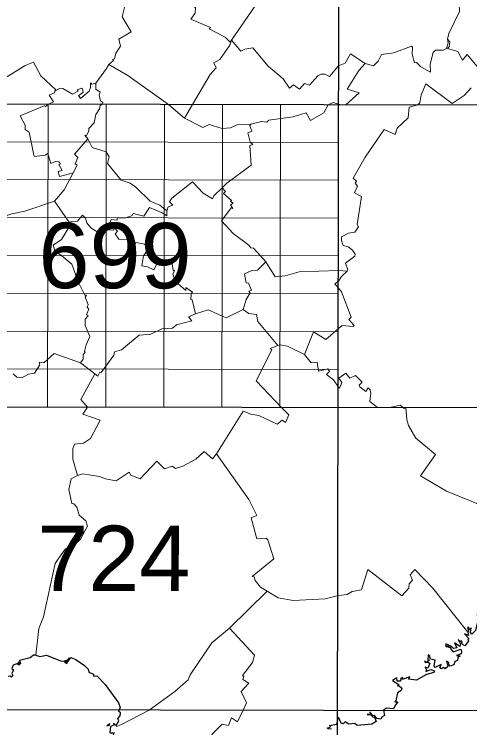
# Model space of a CAD drawing. Extents: x 483847 to 488453, y 4383581 to 4386795.
# Drawn here: x 488155.4 to 488291.2, y 4385556 to 4385768.9 of the extents above; entities that cross this region are included whole.
import ezdxf
from ezdxf.enums import TextEntityAlignment as Align

# ---------------------------------------------------------------- set-up
doc = ezdxf.new("R2010")
doc.units = 0
doc.header["$LTSCALE"] = 3.8
doc.linetypes.add('DOTTED', pattern=[1.5, 0.3, -1.2])
for name, color, linetype, lineweight in [('1', 7, 'Continuous', 13), ('2', 7, 'DOTTED', 13), ('3', 7, 'Continuous', 25)]:
    doc.layers.add(name, color=color, linetype=linetype, lineweight=lineweight)

msp = doc.modelspace()

# ---------------------------------------------------------------- linework, layer by layer
at = {"layer": '1', "lineweight": 25}
for p, q in [((488251.44, 4385380.63), (488252.47, 4385922.58)), ((487836.45, 4385742.71), (488390.69, 4385741.65)), ((487836.28, 4385652.38), (488390.51, 4385651.32)), ((487836.1, 4385562.06), (488390.34, 4385561))]:
    msp.add_line(p, q, dxfattribs=at)
at = {"layer": '1'}
for p, q in [((488165.35, 4385651.74), (488165.52, 4385742.07)), ((488182.67, 4385651.71), (488182.84, 4385742.03)), ((488199.99, 4385651.68), (488200.16, 4385742)), ((488217.31, 4385651.64), (488217.49, 4385741.97)), ((488234.63, 4385651.61), (488234.8, 4385741.93)), ((488252.1, 4385730.61), (488113.54, 4385730.88)), ((488252.08, 4385719.32), (488113.52, 4385719.58)), ((488252.06, 4385708.03), (488113.5, 4385708.3)), ((488252.04, 4385696.74), (488113.48, 4385697)), ((488252.02, 4385685.45), (488113.45, 4385685.72)), ((488252, 4385674.16), (488113.43, 4385674.42)), ((488251.98, 4385662.87), (488113.41, 4385663.13))]:
    msp.add_line(p, q, dxfattribs=at)
at = {"layer": '3', "lineweight": 13}
for p, q in [((488182.87, 4385752.64), (488179.74, 4385748.27)), ((488206.19, 4385737.81), (488201.41, 4385741.93)), ((488252.94, 4385741.87), (488252.13, 4385742.06)), ((488254.34, 4385741.87), (488252.94, 4385741.87)), ((488167.44, 4385713.07), (488171.98, 4385706.56)), ((488182.88, 4385704.56), (488182.76, 4385703.83)), ((488228.86, 4385696.74), (488230.45, 4385694.99)), ((488263.74, 4385651.55), (488267.38, 4385651.56)), ((488230.78, 4385596.71), (488219.58, 4385585.66))]:
    msp.add_line(p, q, dxfattribs=at)
for points in [[(488220.21, 4385761.13), (488228.13, 4385772.7), (488232.82, 4385777.75), (488239.16, 4385785.97), (488239.66, 4385785.89), (488240.55, 4385787.05)], [(488199.2, 4385781.34), (488200.15, 4385779.29), (488200.39, 4385776.63), (488201.82, 4385774.42), (488203.14, 4385774.79), (488203.29, 4385775.73), (488204.67, 4385774.91), (488204.43, 4385774.47), (488207.94, 4385772.21), (488209.43, 4385770.78), (488209.32, 4385769.17), (488208.03, 4385767.44), (488213.88, 4385764.91), (488213.53, 4385764.55), (488218.26, 4385761.99), (488219.77, 4385760.56), (488220.21, 4385761.13)], [(488190.94, 4385776.16), (488189.53, 4385775.57), (488188.44, 4385774.48), (488187.53, 4385772.28), (488188.32, 4385770.85), (488187.6, 4385768.1), (488190.22, 4385763.57), (488186.56, 4385761.41), (488187.11, 4385759.29), (488185.74, 4385757.3), (488185.26, 4385755.51), (488184.68, 4385755.33), (488184.99, 4385755.05), (488183.63, 4385753.87), (488182.87, 4385752.64)], [(488289.37, 4385776.95), (488289.54, 4385775.88), (488288.46, 4385773.74), (488288.11, 4385772.01), (488288.17, 4385769.68), (488285.03, 4385763.14), (488284.6, 4385761.41)], [(488220.21, 4385761.13), (488219.67, 4385759.59), (488216.71, 4385755.4), (488214.9, 4385754.32), (488215.58, 4385752.84), (488213.86, 4385750.9), (488208.54, 4385741.92)], [(488220.21, 4385761.13), (488222.99, 4385757.82), (488224.17, 4385758.43), (488226.59, 4385758.8), (488231.1, 4385753.33), (488235.59, 4385749.63), (488237.46, 4385746.82), (488238.65, 4385747.8), (488240.51, 4385746.55), (488241.92, 4385748.2), (488243.49, 4385747.75), (488245.97, 4385750.53), (488246.96, 4385751.03), (488248, 4385750.97), (488249.38, 4385750.24), (488252.13, 4385753.5)], [(488284.6, 4385761.41), (488284.82, 4385760.34), (488284.3, 4385758.65), (488283.28, 4385758.15), (488281.03, 4385758.11), (488280.3, 4385757.41), (488279.42, 4385753.98), (488279.57, 4385751.54), (488276.66, 4385753.14), (488275.39, 4385754.5), (488274.74, 4385754.41), (488274.1, 4385757), (488274.19, 4385759.07), (488273.86, 4385759.37), (488268.65, 4385757.32), (488264.89, 4385756.83), (488263.98, 4385754.82), (488262.51, 4385753.5), (488260.05, 4385754.13)], [(488284.6, 4385761.41), (488285.27, 4385760.6), (488285.14, 4385759.17), (488284.57, 4385758.65), (488287.69, 4385757.73), (488289.13, 4385755.16), (488290.47, 4385756.9), (488295.44, 4385750.84)], [(488260.05, 4385754.13), (488255.65, 4385757.08), (488254.12, 4385754.29), (488252.13, 4385753.5)], [(488167.53, 4385745.92), (488167.8, 4385746.29), (488163.29, 4385750.45), (488161.13, 4385754.57), (488158.69, 4385753.6), (488153.35, 4385750.3), (488151.64, 4385751.38)], [(488183.63, 4385753.87), (488189.28, 4385750.6), (488201.41, 4385741.93)], [(488260.05, 4385754.13), (488258.18, 4385752.05), (488254.71, 4385746.47), (488258.28, 4385745.37), (488254.34, 4385741.87)], [(488179.74, 4385748.27), (488178.55, 4385747.96), (488178.1, 4385748.41), (488178.17, 4385747.03), (488177.74, 4385745.92), (488175.13, 4385743.73), (488174.55, 4385744.59), (488175.95, 4385745.5), (488175.77, 4385746.65), (488175.46, 4385746.8), (488174.13, 4385746.28), (488174.42, 4385745.95), (488172.72, 4385745.01), (488169.9, 4385746.75), (488169.07, 4385746.77), (488167.53, 4385745.92)], [(488179.74, 4385748.27), (488179.77, 4385746.53), (488181.02, 4385745.63), (488180.72, 4385744.78), (488181.14, 4385742.9), (488181.8, 4385742.63), (488181.51, 4385741.96)], [(488291.72, 4385746.88), (488289.56, 4385744.65), (488286.02, 4385742.23), (488278.18, 4385748.08), (488276.81, 4385744.8), (488276.4, 4385742.39), (488275.8, 4385741.88)], [(488167.53, 4385745.92), (488167.38, 4385745.42), (488165.82, 4385744.74), (488167.09, 4385742.69), (488165.64, 4385742.01)], [(488165.64, 4385742.01), (488164.67, 4385741.33), (488164.3, 4385741.58), (488157.18, 4385738.51), (488158.67, 4385735.77), (488158.65, 4385734.48), (488159.84, 4385733.64), (488161.2, 4385726.8), (488161.41, 4385726.4), (488164.58, 4385726.77), (488165.45, 4385727.34), (488166.31, 4385724.38), (488167.56, 4385724.96), (488168.72, 4385724.85), (488169.16, 4385724.2), (488168.73, 4385724.06), (488169.66, 4385722.2), (488168.52, 4385721.98), (488168.84, 4385720.48), (488172.99, 4385721.58)], [(488181.51, 4385741.96), (488180.97, 4385741.62), (488180.79, 4385740.64), (488179.76, 4385738.93), (488179.18, 4385736.44), (488177.67, 4385734.77), (488177.65, 4385733.94), (488176.93, 4385732.73), (488176.42, 4385732.78), (488177.32, 4385731.73)], [(488225.99, 4385736.06), (488221.89, 4385735.87), (488219.86, 4385734.99), (488217.42, 4385734.73), (488213.57, 4385735.98), (488211.65, 4385735.09), (488206.19, 4385737.81), (488208.54, 4385741.92)], [(488225.99, 4385736.06), (488229.14, 4385736.86), (488230.71, 4385736.63), (488231.34, 4385737.24), (488238.57, 4385738.25), (488242.47, 4385739.4), (488243.73, 4385737.13), (488247.74, 4385739.4), (488249.07, 4385741.87)], [(488252.13, 4385742.06), (488250.48, 4385742.54), (488249.07, 4385741.87)], [(488275.8, 4385741.88), (488273.2, 4385741.15), (488272.87, 4385738), (488269.56, 4385734.91), (488269.01, 4385733.03), (488265.72, 4385734.46), (488260.05, 4385726.19), (488256.45, 4385720), (488257.51, 4385719.05), (488257.11, 4385718.51), (488257.76, 4385717.61), (488256.84, 4385715.54), (488258.98, 4385714.46), (488257.65, 4385706.15), (488258.04, 4385705.45), (488256.99, 4385703.81), (488255.04, 4385703.5), (488253.01, 4385702.47), (488252.98, 4385701.32), (488253.48, 4385699.88), (488255.01, 4385699.45), (488256.3, 4385698.51), (488257.11, 4385697.33), (488256.96, 4385696.71)], [(488217.44, 4385717.08), (488218.77, 4385718.45), (488226.04, 4385723.83), (488225.68, 4385729.71), (488226.55, 4385730.03), (488225.79, 4385730.74), (488225.02, 4385733.46), (488226.23, 4385734.01), (488225.64, 4385735.61), (488225.99, 4385736.06)], [(488177.32, 4385731.73), (488173.37, 4385727.15), (488174.4, 4385726.12), (488173.57, 4385724.25), (488174.17, 4385723.81), (488172.99, 4385721.58)], [(488177.32, 4385731.73), (488178.65, 4385729.11), (488182.82, 4385727.84)], [(488182.82, 4385727.84), (488183.73, 4385726.3), (488183.23, 4385724.38), (488187.28, 4385719.4), (488189.92, 4385718.48), (488191.67, 4385717.25), (488195.94, 4385713.11), (488198.79, 4385711.92), (488200.94, 4385710.23)], [(488172.99, 4385721.58), (488170.28, 4385716.46), (488167.44, 4385713.07)], [(488200.94, 4385710.23), (488201.31, 4385711.45), (488202.74, 4385711.93), (488201.65, 4385712.87), (488202.35, 4385714.02), (488208.52, 4385718.83), (488211.77, 4385715.47), (488214.57, 4385713.81), (488214.97, 4385714.68), (488217.44, 4385717.08)], [(488217.44, 4385717.08), (488218.36, 4385715.96), (488217.8, 4385715.37), (488220.18, 4385713.34), (488219.87, 4385713.04), (488220.64, 4385712.45), (488219.94, 4385712.01), (488220.61, 4385710.93), (488220.11, 4385711.07), (488217.2, 4385707.18), (488220.71, 4385703.44), (488225.36, 4385699.95), (488225.96, 4385699.14), (488226.76, 4385699.07), (488228.86, 4385696.74)], [(488167.44, 4385713.07), (488158.57, 4385710.07), (488154.66, 4385709.36), (488152.11, 4385708.38), (488150.26, 4385711.36), (488146.26, 4385709.98), (488146.02, 4385710.9), (488144.44, 4385710.34), (488140.68, 4385707.94), (488139.48, 4385709.35), (488134.38, 4385707.9)], [(488182.88, 4385704.56), (488184.31, 4385707.61), (488186.01, 4385707.44), (488186.21, 4385708.1), (488188.65, 4385708.13), (488190.57, 4385708.83), (488190.88, 4385709.38), (488194.06, 4385708.61), (488195.76, 4385711.19), (488199.47, 4385709.66), (488200.88, 4385708.68), (488200.94, 4385710.23)], [(488171.98, 4385706.56), (488172.22, 4385706.94), (488174.28, 4385707.16), (488175.7, 4385708.91), (488176.68, 4385708.05), (488177.07, 4385706.67), (488178.28, 4385705.16), (488181.11, 4385703.33), (488182.76, 4385703.83)], [(488171.98, 4385706.56), (488172.29, 4385706.21), (488169.5, 4385701.66), (488166.99, 4385699.99), (488167.63, 4385698.21), (488169.6, 4385696.83)], [(488182.88, 4385704.56), (488185.12, 4385704.48), (488185.15, 4385705.23), (488186.2, 4385704.12), (488185.45, 4385703.35), (488186.56, 4385701.78), (488189.95, 4385701.63), (488191.29, 4385700.44), (488191.74, 4385700.79), (488194.25, 4385700.27), (488195.42, 4385698.88), (488193.92, 4385696.78)], [(488169.6, 4385696.83), (488172.53, 4385694.28), (488174.45, 4385689), (488176.46, 4385685.01), (488176.96, 4385685.03), (488176.56, 4385684.42), (488177.44, 4385682.24), (488177.18, 4385681.47), (488177.6, 4385680.92), (488176.95, 4385679.28), (488177.42, 4385678.9), (488176.52, 4385677.86), (488176.52, 4385676.02), (488177.93, 4385672.7), (488176.84, 4385670.28), (488176.31, 4385668.26), (488176.59, 4385668.09), (488175.96, 4385667.22), (488175.99, 4385665.95), (488175.14, 4385664.85)], [(488193.92, 4385696.78), (488193.43, 4385693.85), (488195.13, 4385693.53), (488196.99, 4385692.62), (488198.68, 4385695.85), (488201.41, 4385695.05), (488201.74, 4385695.24), (488201.77, 4385694.77), (488202.42, 4385695.01), (488202.81, 4385692.44), (488203.16, 4385692.37), (488202.69, 4385691.33), (488203.34, 4385689.24), (488206.58, 4385686.44), (488206.58, 4385687.33), (488208.54, 4385685.98), (488208.14, 4385685.43), (488208.09, 4385683.71), (488208.5, 4385683.67), (488209.47, 4385679.46)], [(488256.96, 4385696.71), (488254.23, 4385694.62), (488254.88, 4385692.6), (488254.67, 4385692.19), (488252.11, 4385692.42)], [(488230.45, 4385694.99), (488227.98, 4385692.5), (488226.05, 4385692.3), (488224.03, 4385691.43), (488224.56, 4385688.73), (488225.24, 4385688.65), (488226.2, 4385686.52), (488225.37, 4385686.22), (488225.73, 4385685.74), (488224.56, 4385683.76), (488223.68, 4385680.79)], [(488230.45, 4385694.99), (488233.21, 4385690.49), (488236.2, 4385690.77), (488240.35, 4385692.03), (488252.11, 4385692.42)], [(488254.67, 4385692.19), (488252.95, 4385690.65), (488252.11, 4385689.25)], [(488252.11, 4385689.25), (488251.03, 4385688.45), (488252.11, 4385687.12)], [(488252.11, 4385687.12), (488253.04, 4385686.01), (488255.87, 4385678.46), (488255.16, 4385677.75), (488256.76, 4385676.05), (488256.44, 4385675.69), (488253.15, 4385675.97), (488252.1, 4385675.15)], [(488209.47, 4385679.46), (488207.41, 4385678.55), (488208.31, 4385677.43), (488203.78, 4385676.23), (488202.62, 4385675.18), (488199.39, 4385674.96), (488196.11, 4385673.45), (488192.7, 4385673.13), (488187.34, 4385668.77), (488185.25, 4385668.14), (488185.05, 4385667.14), (488182.68, 4385663.82)], [(488223.68, 4385680.79), (488218.57, 4385678.33), (488213.2, 4385680.64), (488209.47, 4385679.46)], [(488223.68, 4385680.79), (488225.41, 4385679.63), (488227.63, 4385679.28), (488228.02, 4385677.18), (488233.98, 4385670.03)], [(488252.1, 4385675.15), (488248.36, 4385671.8), (488244.62, 4385674.1), (488241.93, 4385667.32)], [(488233.98, 4385670.03), (488231.72, 4385669.18), (488232.2, 4385668.73), (488227.58, 4385659.47), (488235.12, 4385651.57)], [(488241.93, 4385667.32), (488236.85, 4385669.8), (488234.57, 4385670.27), (488233.98, 4385670.03)], [(488155.03, 4385661.61), (488156.12, 4385660.59), (488157.68, 4385660.36), (488159.68, 4385661.52), (488161.42, 4385661.76), (488162.99, 4385664.28), (488162.78, 4385665.11), (488164.26, 4385664.83), (488167.34, 4385667.65), (488175.14, 4385664.85), (488179.41, 4385661.55)], [(488241.93, 4385667.32), (488243.99, 4385664.89), (488245.79, 4385665.03), (488246.09, 4385662.38), (488248.88, 4385663.07), (488249.42, 4385662.24), (488248.57, 4385661.42), (488250.57, 4385659.78), (488252.1, 4385657.64)], [(488182.68, 4385663.82), (488181.34, 4385662.02), (488180.95, 4385662.11), (488180.37, 4385660.91), (488179.41, 4385661.55)], [(488179.41, 4385661.55), (488175.21, 4385653.96), (488177.22, 4385651.65)], [(488252.1, 4385657.64), (488252.4, 4385657.27), (488253.14, 4385658.98), (488252.21, 4385660.29), (488254.26, 4385661.74), (488255.48, 4385660.3), (488257.14, 4385661.1), (488259.19, 4385659.07), (488258.28, 4385658.25), (488258.5, 4385657.73), (488260.28, 4385656.33), (488260.92, 4385657.36), (488261.51, 4385656.81), (488261.77, 4385655.84), (488261.44, 4385653.35), (488263.74, 4385651.55)], [(488174.26, 4385631.26), (488172.91, 4385636.17), (488172.85, 4385639.35), (488173.33, 4385640.63), (488176.04, 4385640.86), (488178.13, 4385642.27), (488181.02, 4385647.76), (488175.87, 4385649.57), (488177.22, 4385651.65)], [(488267.38, 4385651.56), (488270.45, 4385652.23), (488271.35, 4385651.56)], [(488215.69, 4385637.76), (488223.71, 4385650.47), (488225.92, 4385649.59), (488228.3, 4385649.2), (488233.82, 4385646.6), (488235.27, 4385647.74), (488236.27, 4385647.03), (488237.31, 4385649.36), (488235.12, 4385651.57)], [(488271.35, 4385651.56), (488271.67, 4385651.26), (488272.21, 4385651.43), (488272.45, 4385647.98), (488273.02, 4385646.18), (488275.13, 4385642.37), (488281.06, 4385637.53), (488276.54, 4385631.14), (488284.34, 4385626.54), (488305.36, 4385618.01), (488306.32, 4385618.01)], [(488182.6, 4385630.29), (488185.82, 4385629.68), (488189.64, 4385632.26), (488190.15, 4385631.39), (488192.95, 4385630.22), (488197.95, 4385635.51), (488200.24, 4385633.22), (488202.51, 4385634.06), (488203.46, 4385633.3), (488205.7, 4385634.07), (488209.58, 4385636.1), (488212.08, 4385638.38), (488214.53, 4385636.22), (488215.69, 4385637.76)], [(488215.69, 4385637.76), (488225.39, 4385624.05), (488227.77, 4385619.31), (488226.1, 4385618.61), (488227.77, 4385612.4), (488230.55, 4385612.57), (488230.99, 4385612.07), (488232.79, 4385606.4)], [(488174.26, 4385631.26), (488172.41, 4385630.27), (488171.68, 4385627.03), (488172.59, 4385622.88), (488173.18, 4385622.78), (488174.04, 4385621.84), (488174.75, 4385619.44), (488176.78, 4385617.77), (488177.23, 4385616.09), (488175.13, 4385612.28), (488173.02, 4385610.23), (488170.72, 4385609.42), (488168.57, 4385606.52)], [(488174.26, 4385631.26), (488175.84, 4385631.72), (488180.86, 4385630.97), (488182.6, 4385630.29)], [(488161.84, 4385577.6), (488162.74, 4385585.63), (488164.11, 4385589.12), (488167.55, 4385605.04), (488168.57, 4385606.52)], [(488230.78, 4385596.71), (488228.86, 4385597.93), (488227.28, 4385599.93), (488226.96, 4385601.03), (488226.35, 4385601.16), (488232.79, 4385606.4)], [(488252.08, 4385595.48), (488254.72, 4385595.77), (488256.17, 4385596.62), (488258.94, 4385597.13), (488260.85, 4385603.17), (488271, 4385595.36), (488273.12, 4385597.64), (488273.15, 4385598.93), (488274.17, 4385600.03), (488273.46, 4385601.64), (488274.92, 4385603.21), (488280.28, 4385597.68), (488290.67, 4385584.48)], [(488230.78, 4385596.71), (488234.1, 4385594.78), (488238.56, 4385593.98), (488248.15, 4385594.46), (488252.08, 4385595.48)], [(488219.58, 4385585.66), (488214.34, 4385581.3), (488207.91, 4385571.8), (488207.26, 4385570.29), (488203.24, 4385566.8), (488195.61, 4385561.28)], [(488219.58, 4385585.66), (488227.04, 4385577.66), (488226.44, 4385575.51), (488223.46, 4385571.59), (488223.87, 4385571.33), (488223.62, 4385570.39), (488225.34, 4385569.32), (488223.12, 4385566.84), (488224.71, 4385563.44), (488223.71, 4385561.25)], [(488195.61, 4385561.28), (488187.39, 4385556.93), (488185.88, 4385556.39), (488185.77, 4385556.66)], [(488223.71, 4385561.25), (488222.02, 4385557.74), (488220.17, 4385558.96), (488219.29, 4385556.68), (488217.36, 4385557.05), (488214.32, 4385553.98), (488217.28, 4385549.47), (488217.67, 4385546.81), (488219.62, 4385544.09), (488214.43, 4385542.89), (488210.32, 4385540.99), (488204.63, 4385539.36), (488202.88, 4385537.6), (488202.95, 4385537.22)]]:
    msp.add_lwpolyline(points, dxfattribs=at)
at = {"layer": '3'}
for points in [[(488294.09, 4385589.86), (488293.78, 4385590.7), (488293.78, 4385589.85), (488293.38, 4385589.68), (488293.84, 4385589.53), (488294.09, 4385588.79), (488294.39, 4385589.15), (488294.61, 4385588.84), (488294.12, 4385587.5), (488293.4, 4385586.84), (488292.94, 4385584.96), (488291.84, 4385583.89), (488291.43, 4385584.4), (488291.64, 4385585.83), (488291.25, 4385585.25), (488290.84, 4385586.02), (488290.56, 4385585.9), (488290.91, 4385584.89), (488290.67, 4385584.48)], [(488290.67, 4385584.48), (488290.89, 4385583.55), (488289.72, 4385584.05), (488291.1, 4385582.51), (488290.65, 4385582.4), (488290.83, 4385581.86), (488289.74, 4385580.47), (488289.09, 4385580.79), (488288.82, 4385581.93), (488288.43, 4385581.71), (488287.84, 4385582.37), (488288.5, 4385581), (488288.26, 4385580.22), (488286.75, 4385581.33), (488287.35, 4385579.88), (488286.42, 4385579.61), (488285.73, 4385580.31)], [(488285.73, 4385580.31), (488284.08, 4385581.01), (488284.09, 4385580.24), (488284.36, 4385580.57), (488284.25, 4385580.09), (488284.72, 4385580.48), (488284.54, 4385580.15), (488284.86, 4385580.41), (488284.86, 4385580), (488285.07, 4385580.31), (488284.9, 4385579.99), (488285.59, 4385580), (488285.41, 4385579.72), (488286.28, 4385578.65), (488288.57, 4385579.41), (488288.84, 4385578.62), (488288.66, 4385578.08), (488287.32, 4385577.56), (488288.36, 4385577.43), (488287.71, 4385576.88), (488287.63, 4385576.08), (488286.78, 4385575.74), (488286.51, 4385574.77), (488285.43, 4385574.37), (488284.9, 4385574.92)], [(488161.84, 4385577.6), (488161.11, 4385577.64), (488160.18, 4385576.84), (488156.93, 4385576.01), (488157.12, 4385575.48), (488156.61, 4385575.61), (488156.95, 4385575.3), (488156.57, 4385575.45), (488156.81, 4385575.15), (488156.36, 4385575.09), (488156.72, 4385574.84), (488157.35, 4385575.31), (488156.74, 4385574.69), (488156.12, 4385575.1), (488155.03, 4385574.63), (488154.7, 4385573.63), (488155.19, 4385573.31), (488154.66, 4385572.16), (488154.96, 4385571.61), (488154.52, 4385571.09), (488154.36, 4385571.43), (488153.62, 4385571.3)], [(488161.84, 4385577.6), (488162.98, 4385577.27), (488165.06, 4385577.64), (488169.2, 4385575.94), (488170.17, 4385575.88), (488170.84, 4385575.18), (488171.27, 4385575.38), (488170.39, 4385575.96), (488170.87, 4385575.71), (488170.7, 4385576), (488171.01, 4385575.82), (488170.84, 4385576.11), (488171.28, 4385576.05), (488171.83, 4385576.9), (488172.03, 4385576.59)], [(488284.9, 4385574.92), (488284.97, 4385575.36), (488284.36, 4385575.84), (488284.76, 4385574.24), (488283.96, 4385573.53), (488283.44, 4385573.92), (488282.79, 4385573.57), (488282.36, 4385573.86), (488282.76, 4385574.85), (488280.93, 4385574.01), (488280.63, 4385574.47), (488280.97, 4385576.11), (488279.51, 4385576.42), (488279.22, 4385577.52), (488278.83, 4385577.71), (488278.77, 4385576.11), (488279.25, 4385576.16), (488278.34, 4385575.46), (488277.76, 4385575.82), (488278.04, 4385575.45)], [(488172.03, 4385576.59), (488171.17, 4385575.52), (488172.24, 4385576.98), (488173.79, 4385576.34), (488176.36, 4385574.59), (488177.43, 4385573.49), (488177.64, 4385572.53), (488179.02, 4385572.01), (488179.02, 4385571.35), (488180.01, 4385571.49), (488182.47, 4385568.86)], [(488278.04, 4385575.45), (488278.88, 4385575.54), (488279.32, 4385575.16), (488278.76, 4385573.77), (488277.91, 4385574.07), (488278.36, 4385573.3), (488278.14, 4385572.81), (488279.64, 4385573.37), (488280.74, 4385572.93), (488280.58, 4385572.46), (488278.36, 4385571.91), (488275.36, 4385570.16), (488272.98, 4385570.5), (488273.4, 4385571.15), (488271.42, 4385570.45), (488271.1, 4385570.45), (488271.25, 4385571.11), (488271.06, 4385570.89)], [(488271.06, 4385570.89), (488270.65, 4385570.81), (488270.59, 4385569.87), (488269.6, 4385569.89), (488269.55, 4385570.84), (488268.18, 4385570.06), (488270.11, 4385568.93), (488269.74, 4385568.46), (488270.19, 4385568.53), (488271.04, 4385567.8), (488270.82, 4385567.13), (488269.73, 4385566.46), (488269.24, 4385564), (488268.86, 4385563.73), (488269.76, 4385563.74), (488269.24, 4385562.98)], [(488182.47, 4385568.86), (488186.53, 4385563.41), (488186.99, 4385562.04), (488186.71, 4385561.3)], [(488269.24, 4385562.98), (488268.51, 4385561.66), (488266.47, 4385561.85), (488265.49, 4385561.22)], [(488185.77, 4385556.66), (488186.6, 4385558.02), (488186.24, 4385558.72), (488186.99, 4385559.5), (488187.1, 4385560.45), (488186.55, 4385560.82), (488186.71, 4385561.3)], [(488265.49, 4385561.22), (488265.87, 4385559.62), (488265.1, 4385559.29), (488264.69, 4385558.52), (488263.56, 4385558.76), (488262.87, 4385559.63), (488262.37, 4385559.55), (488261.42, 4385560.75), (488261.75, 4385560), (488260.67, 4385559.96), (488261.81, 4385559.89), (488262.26, 4385559.22), (488262.83, 4385559.11), (488263.32, 4385557.86), (488262.09, 4385557.06), (488260.97, 4385556.92)], [(488250.05, 4385555.61), (488248.93, 4385555.66), (488248.85, 4385555.98), (488249.65, 4385556.12), (488249.7, 4385556.54), (488249.32, 4385556.69), (488251.6, 4385557.06), (488252.06, 4385559.12)], [(488260.97, 4385556.92), (488257.66, 4385556.69), (488256.97, 4385557.26), (488255.19, 4385557.07), (488254.09, 4385557.75), (488253.49, 4385557.2), (488252.89, 4385557.32), (488252.06, 4385559.12)], [(488185.77, 4385556.66), (488184.95, 4385557.28), (488185.09, 4385556.74), (488184.15, 4385556.38), (488183.94, 4385554.47), (488185.2, 4385554.44), (488184.87, 4385553.88), (488185.24, 4385553.61), (488184.98, 4385553.03), (488184.1, 4385552.6), (488184.83, 4385552.4), (488184.84, 4385551.46), (488188.04, 4385550.87), (488187.98, 4385550.17), (488187.24, 4385549.82), (488187.8, 4385549.63)]]:
    msp.add_lwpolyline(points, dxfattribs=at)
msp.add_lwpolyline([(488183.89, 4385557.13), (488182.97, 4385556.57), (488183.79, 4385556.73)], close=True, dxfattribs=at)

# ---------------------------------------------------------------- texts
at = {"layer": '2', "width": 1.05}
for s, p in [('699', (488185.44, 4385687.12)), ('724', (488185.07, 4385596.79))]:
    msp.add_text(s, height=19.5, rotation=359.891, dxfattribs=at).set_placement(p, align=Align.CENTER)

doc.saveas('drawing.dxf')
